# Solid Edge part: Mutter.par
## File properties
Sűrűség: 0,000 kg/m^3
Pontosság: 0,990
Author: ahadarics
Last saved by: psaghy
Revision: 77
Username: ahadarics
Dokumentum tartalom típus: 0
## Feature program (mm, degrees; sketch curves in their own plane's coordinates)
base feature "unnamed BaseFeature 1"
sketch for "Furat_1" plane through (9, 0, 0) normal (1, 0, 0) x-axis (0, 1, 0)
  hole centre (0, 0) bore radius 9.188
hole "Furat_1" through  StartChamferOffset = 0.47 mm; StartChamferAngle = 45 deg
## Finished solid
Body 1: solid body, 23 faces, 47 edges, 26 vertices.
  Faces by surface: cone 14, plane 8, cylinder 1
  Edges by curve: spline 24, circle 16, line 7
Bounding box of the edges (mm): 9.000 x 34.641 x 30.000, from (0, -17.3205, -15) to (9, 17.3205, 15).
Cylindrical faces by radius (mm): R9.188 x1
Conical faces (half-angle, radius in mm at the cone's reference point): 45 deg R9.658 x1, 60 deg R9.5939 x1, 60 deg R16.1603 x12
Planar faces by outward normal: +x 1, +z 1, -x 1, -z 1, oblique 4
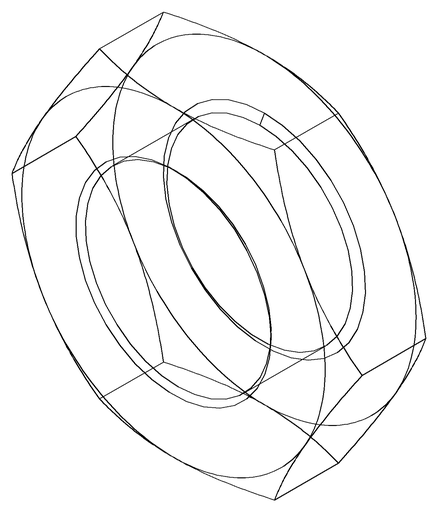
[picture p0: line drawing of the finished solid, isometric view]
